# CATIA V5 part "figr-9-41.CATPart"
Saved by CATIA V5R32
Part number: Part1
Bounding box of the stored display mesh (mm): x -40 to 40, y -20.616 to 191.034, z 0 to 131.022
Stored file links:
  D:\PROJECTS\Project 2022\CATIA V5 6R 2022\Resources\Part Files\c09_catia_v5_6r2022_prt\c09_catia_v5_6r2022_prt\figr-9-41.CATPart
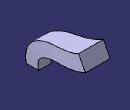
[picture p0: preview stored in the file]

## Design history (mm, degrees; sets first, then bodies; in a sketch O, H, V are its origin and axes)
Set1
  Plane1: type Normal, Curve Sketch2, RefPoint vertex of Sketch2
Body1 (main body)
  Sketch1 on xy-plane, origin (0, 0, 0), H (1, 0, 0), V (0, 1, 0)
    line L1 (20, 20) -> (20, -20)
    line L2 (20, -20) -> (-20, -20)
    line L3 (-20, -20) -> (-20, 20)
    line L4 (-20, 20) -> (20, 20)
    vertical: L1 V, L3 V
    horizontal: L2 H, L4 H
    equidistance: L1 L3 O, L2 L4 O
  Sketch2 on yz-plane, origin (0, 0, 0), H (0, 1, 0), V (0, 0, 1)
    spline S1 through (0, 0) (20, 60) (60, 80) (120, 90) (180, 110)
    point P1 (0, 0)
    coincidence: P1 O
  Sketch3 on Plane1, origin (0, 186.3865, 97.8327), H (1, 0, 0), V (0, -0.4648, 0.8854)
    point P1 (0, 13.7415)
    line L1 (40, 37.4831) -> (40, -10)
    line L2 (40, -10) -> (-40, -10)
    line L3 (-40, -10) -> (-40, 37.4831)
    line L4 (-40, 37.4831) -> (40, 37.4831)
    reference projected point E1 (0, 13.7415) from vertex of Sketch2
    coincidence: P1 V, P1 E1
    vertical: L1 V, L3 V
    horizontal: L2 H, L4 H
    equidistance: L1 L3 P1, L2 L4 P1
  Loft1: Sections (Sketch1; Sketch3), Spine Sketch2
